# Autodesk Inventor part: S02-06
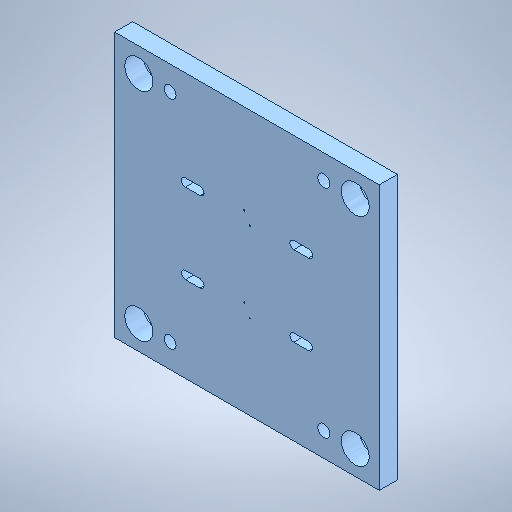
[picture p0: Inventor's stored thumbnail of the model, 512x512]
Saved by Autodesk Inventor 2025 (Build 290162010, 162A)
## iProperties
Created: 2025-04
Part Number: S02-06
Material: Všeobecné
Document SubType Name: Modeling
Designer: Patrik
Density: 1 g/cm^3
Appearance: Výchozí
Description: Deska opěrná levá
Stock Number: F 60 /396 396/ 27/1730
Mass: 4029.75 g
Surface Area: 3707.1 cm^2
Volume: 4029.75 cm^3
User Status: 1730
Author: Patrik
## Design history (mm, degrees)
feature "Base1"
feature "Vyřezání2"
feature "Vyřezání4"
sketch "Náčrt1"
  geometry: L1 (105.9, -255.974)-(127.9, -255.974) reference; L2 (127.9, -267.974)-(105.9, -267.974) reference; L3 (105.9, -135.974)-(127.9, -135.974) reference; L4 (127.9, -147.974)-(105.9, -147.974) reference; L5 (290.1, -135.974)-(268.1, -135.974) reference; L6 (268.1, -147.974)-(290.1, -147.974) reference; L7 (290.1, -255.974)-(268.1, -255.974) reference; L8 (268.1, -267.974)-(290.1, -267.974) reference; A1 r 6 centre (127.9, -261.974) between (127.9, -267.974) and (127.9, -255.974) reference; A2 r 6 centre (105.9, -261.974) between (105.9, -255.974) and (105.9, -267.974) reference; A3 r 6 centre (127.9, -141.974) between (127.9, -147.974) and (127.9, -135.974) reference; A4 r 6 centre (105.9, -141.974) between (105.9, -135.974) and (105.9, -147.974) reference; A5 r 6 centre (290.1, -141.974) between (290.1, -147.974) and (290.1, -135.974) reference; A6 r 6 centre (268.1, -141.974) between (268.1, -135.974) and (268.1, -147.974) reference; A7 r 6 centre (290.1, -261.974) between (290.1, -267.974) and (290.1, -255.974) reference; A8 r 6 centre (268.1, -261.974) between (268.1, -255.974) and (268.1, -267.974) reference; 1 further point
extrude "Vysunutí1" cut sketch "Náčrt1" distance "d0" = 15; taper "d1" = 0 deg
feature "Vyřezání8"
sketch "Náčrt5"
  geometry: L1 (70.5, 252.587)-(68, 251.143) reference; L2 (70.5, 255.473)-(70.5, 252.587) reference; L3 (68, 256.917)-(70.5, 255.473) reference; L4 (65.5, 255.473)-(68, 256.917) reference; L5 (65.5, 252.587)-(65.5, 255.473) reference; L6 (68, 251.143)-(65.5, 252.587) reference; L7 (70.5, 132.587)-(68, 131.143) reference; L8 (70.5, 135.473)-(70.5, 132.587) reference; L9 (68, 136.917)-(70.5, 135.473) reference; L10 (65.5, 135.473)-(68, 136.917) reference; L11 (65.5, 132.587)-(65.5, 135.473) reference; L12 (68, 131.143)-(65.5, 132.587) reference; L13 (330.5, 132.587)-(328, 131.143) reference; L14 (330.5, 135.473)-(330.5, 132.587) reference; L15 (328, 136.917)-(330.5, 135.473) reference; L16 (325.5, 135.473)-(328, 136.917) reference; L17 (325.5, 132.587)-(325.5, 135.473) reference; L18 (328, 131.143)-(325.5, 132.587) reference; L19 (330.5, 252.587)-(328, 251.143) reference; L20 (330.5, 255.473)-(330.5, 252.587) reference; L21 (328, 256.917)-(330.5, 255.473) reference; L22 (325.5, 255.473)-(328, 256.917) reference; L23 (325.5, 252.587)-(325.5, 255.473) reference; L24 (328, 251.143)-(325.5, 252.587) reference; 1 further point
extrude "Vysunutí5" cut sketch "Náčrt5" stored distance "d24" = 10; taper "d25" = 0 deg
node "Těleso1"
node "Promítnutá smyčka5"
node "Promítnutá smyčka6"
node "Promítnutá smyčka7"
node "Promítnutá smyčka8"
feature "Plocha4"
node "Povrch4"
feature "Plocha6"
node "Povrch6"
feature "Plocha16"
node "Povrch16"
